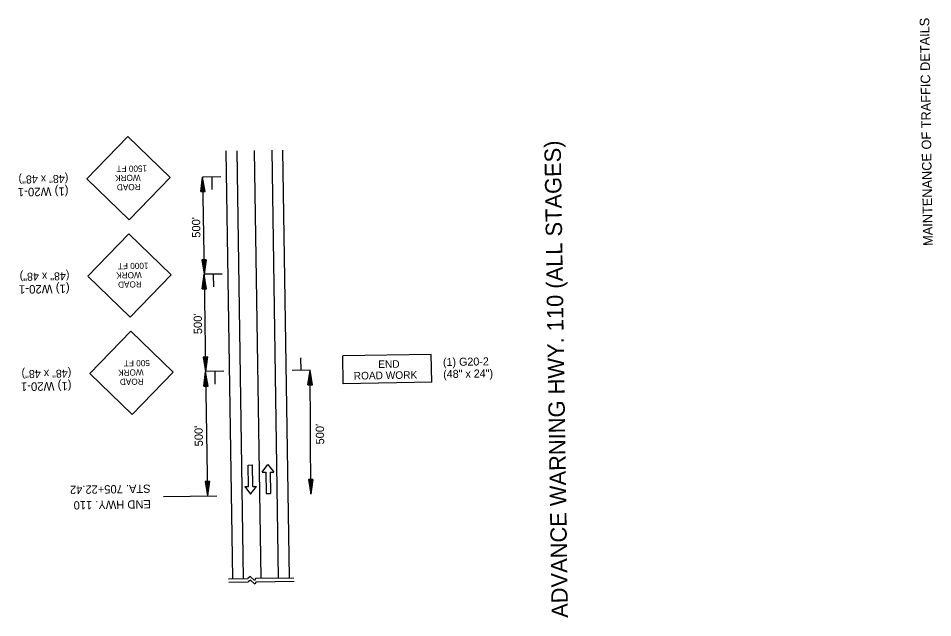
# Model space of a CAD drawing. Extents: x 1770018 to 1773492, y 718230 to 729141.
# Drawn here: x 1770380 to 1771052, y 721562 to 722002 of the extents above; entities that cross this region are included whole.
import ezdxf

# ---------------------------------------------------------------- set-up
doc = ezdxf.new("R2010")
doc.units = 0
for name, color, linetype in [('Default', 7, 'Continuous'), ('R_Border', 7, 'Continuous'), ('R_Dimension', 7, 'Continuous'), ('R_Draft', 7, 'Continuous'), ('R_MOT', 7, 'Continuous')]:
    doc.layers.add(name, color=color, linetype=linetype)

msp = doc.modelspace()

# ---------------------------------------------------------------- linework, layer by layer
at = {"layer": 'Default'}
for p, q in [((1770540.66, 721904.52), (1770545.5, 721590.55)), ((1770553.51, 721904.71), (1770558.35, 721590.75)), ((1770566.37, 721904.91), (1770571.21, 721590.95)), ((1770515.64, 721885.26), (1770516.74, 721813.84)), ((1770516.74, 721813.84), (1770517.84, 721742.42)), ((1770595.14, 721652.54), (1770594.52, 721743.41)), ((1770517.84, 721742.42), (1770519.25, 721651.18)), ((1770548.95, 721673.83), (1770552.16, 721673.88)), ((1770549.19, 721658.07), (1770548.95, 721673.83)), ((1770552.41, 721658.12), (1770552.16, 721673.88)), ((1770559.32, 721668.59), (1770563.52, 721674.22)), ((1770563.52, 721674.22), (1770567.89, 721668.72)), ((1770559.32, 721668.59), (1770562, 721668.63)), ((1770562, 721668.63), (1770562.24, 721652.87)), ((1770565.21, 721668.68), (1770567.89, 721668.72)), ((1770565.21, 721668.68), (1770565.46, 721652.92)), ((1770546.52, 721658.03), (1770549.19, 721658.07)), ((1770546.52, 721658.03), (1770550.89, 721652.54)), ((1770550.89, 721652.54), (1770555.09, 721658.16)), ((1770552.41, 721658.12), (1770555.09, 721658.16)), ((1770486.81, 721650.68), (1770526.09, 721651.28)), ((1770562.24, 721652.87), (1770565.46, 721652.92)), ((1770534.54, 721590.38), (1770548.75, 721590.6)), ((1770554.62, 721590.69), (1770582.69, 721591.13)), ((1770554.85, 721588.12), (1770582.73, 721588.55)), ((1770534.77, 721587.81), (1770548.97, 721588.03))]:
    msp.add_line(p, q, dxfattribs=at)
for points in [[(1770554.62, 721590.69), (1770553.66, 721589.03), (1770550.58, 721591.93), (1770548.75, 721590.6)], [(1770554.85, 721588.12), (1770553.89, 721586.45), (1770550.8, 721589.35), (1770548.97, 721588.03)]]:
    msp.add_lwpolyline(points, dxfattribs=at)
at = {"layer": 'R_Dimension'}
for p, q in [((1770532.66, 721904.39), (1770537.5, 721590.43)), ((1770574.37, 721905.04), (1770579.21, 721591.07))]:
    msp.add_line(p, q, dxfattribs=at)
at = {"layer": 'R_Draft'}
for p, q in [((1770514.2, 721874.53), (1770515.64, 721885.26)), ((1770517.41, 721874.58), (1770515.64, 721885.26)), ((1770514.47, 721874.53), (1770515.67, 721883.47)), ((1770514.74, 721874.53), (1770515.7, 721881.63)), ((1770515.01, 721874.54), (1770515.72, 721879.85)), ((1770515.29, 721874.54), (1770515.75, 721878.03)), ((1770517.15, 721874.57), (1770515.67, 721883.47)), ((1770516.87, 721874.57), (1770515.7, 721881.63)), ((1770516.6, 721874.56), (1770515.72, 721879.85)), ((1770516.33, 721874.56), (1770515.75, 721878.03)), ((1770514.2, 721874.53), (1770517.41, 721874.58)), ((1770515.55, 721874.55), (1770515.78, 721876.24)), ((1770516.06, 721874.55), (1770515.78, 721876.24)), ((1770518.18, 721824.58), (1770514.97, 721824.53)), ((1770514.97, 721824.53), (1770516.74, 721813.84)), ((1770515.24, 721824.54), (1770516.71, 721815.63)), ((1770515.51, 721824.54), (1770516.69, 721817.48)), ((1770515.78, 721824.54), (1770516.66, 721819.26)), ((1770516.05, 721824.55), (1770516.63, 721821.08)), ((1770516.32, 721824.55), (1770516.6, 721822.86)), ((1770516.83, 721824.56), (1770516.6, 721822.86)), ((1770517.1, 721824.56), (1770516.63, 721821.08)), ((1770517.37, 721824.57), (1770516.66, 721819.26)), ((1770517.64, 721824.57), (1770516.69, 721817.48)), ((1770517.92, 721824.58), (1770516.71, 721815.63)), ((1770518.18, 721824.58), (1770516.74, 721813.84)), ((1770515.3, 721803.11), (1770516.74, 721813.84)), ((1770515.57, 721803.11), (1770516.77, 721812.05)), ((1770515.84, 721803.11), (1770516.8, 721810.21)), ((1770518.51, 721803.16), (1770516.74, 721813.84)), ((1770518.25, 721803.15), (1770516.77, 721812.05)), ((1770517.97, 721803.15), (1770516.8, 721810.21)), ((1770516.11, 721803.12), (1770516.83, 721808.43)), ((1770516.39, 721803.12), (1770516.85, 721806.61)), ((1770516.65, 721803.13), (1770516.88, 721804.82)), ((1770517.7, 721803.14), (1770516.83, 721808.43)), ((1770517.43, 721803.14), (1770516.85, 721806.61)), ((1770517.16, 721803.13), (1770516.88, 721804.82)), ((1770515.3, 721803.11), (1770518.51, 721803.16)), ((1770519.28, 721753.16), (1770516.07, 721753.11)), ((1770516.07, 721753.11), (1770517.84, 721742.42)), ((1770516.34, 721753.12), (1770517.81, 721744.21)), ((1770516.61, 721753.12), (1770517.79, 721746.06)), ((1770516.88, 721753.12), (1770517.76, 721747.84)), ((1770517.15, 721753.13), (1770517.73, 721749.66)), ((1770517.43, 721753.13), (1770517.7, 721751.44)), ((1770517.93, 721753.14), (1770517.7, 721751.44)), ((1770518.2, 721753.14), (1770517.73, 721749.66)), ((1770518.48, 721753.15), (1770517.76, 721747.84)), ((1770518.74, 721753.15), (1770517.79, 721746.06)), ((1770519.02, 721753.16), (1770517.81, 721744.21)), ((1770519.28, 721753.16), (1770517.84, 721742.42)), ((1770592.98, 721732.69), (1770594.52, 721743.41)), ((1770596.2, 721732.71), (1770594.52, 721743.41)), ((1770516.4, 721731.69), (1770517.84, 721742.42)), ((1770516.67, 721731.69), (1770517.87, 721740.63)), ((1770516.94, 721731.69), (1770517.9, 721738.79)), ((1770517.21, 721731.7), (1770517.93, 721737.01)), ((1770519.61, 721731.74), (1770517.84, 721742.42)), ((1770519.35, 721731.73), (1770517.87, 721740.63)), ((1770519.07, 721731.73), (1770517.9, 721738.79)), ((1770518.81, 721731.72), (1770517.93, 721737.01)), ((1770593.25, 721732.69), (1770594.53, 721741.62)), ((1770593.53, 721732.69), (1770594.54, 721739.78)), ((1770593.79, 721732.69), (1770594.55, 721738)), ((1770594.07, 721732.69), (1770594.57, 721736.18)), ((1770595.93, 721732.71), (1770594.53, 721741.62)), ((1770595.66, 721732.71), (1770594.54, 721739.78)), ((1770595.39, 721732.7), (1770594.55, 721738)), ((1770595.12, 721732.7), (1770594.57, 721736.18)), ((1770516.4, 721731.69), (1770519.61, 721731.74)), ((1770517.49, 721731.7), (1770517.95, 721735.19)), ((1770517.76, 721731.71), (1770517.98, 721733.4)), ((1770518.53, 721731.72), (1770517.95, 721735.19)), ((1770518.26, 721731.71), (1770517.98, 721733.4)), ((1770592.98, 721732.69), (1770596.2, 721732.71)), ((1770594.34, 721732.7), (1770594.58, 721734.39)), ((1770594.84, 721732.7), (1770594.58, 721734.39)), ((1770596.59, 721663.28), (1770593.37, 721663.23)), ((1770593.37, 721663.23), (1770595.14, 721652.54)), ((1770593.64, 721663.24), (1770595.12, 721654.33)), ((1770593.91, 721663.24), (1770595.09, 721656.18)), ((1770594.18, 721663.24), (1770595.06, 721657.96)), ((1770594.45, 721663.25), (1770595.03, 721659.78)), ((1770594.73, 721663.25), (1770595.01, 721661.56)), ((1770595.23, 721663.26), (1770595.01, 721661.56)), ((1770595.5, 721663.26), (1770595.03, 721659.78)), ((1770595.78, 721663.27), (1770595.06, 721657.96)), ((1770596.05, 721663.27), (1770595.09, 721656.18)), ((1770596.32, 721663.28), (1770595.12, 721654.33)), ((1770596.59, 721663.28), (1770595.14, 721652.54)), ((1770520.69, 721661.92), (1770517.48, 721661.87)), ((1770517.48, 721661.87), (1770519.25, 721651.18)), ((1770517.74, 721661.87), (1770519.22, 721652.97)), ((1770518.02, 721661.87), (1770519.19, 721654.81)), ((1770518.28, 721661.88), (1770519.16, 721656.59)), ((1770518.56, 721661.88), (1770519.14, 721658.41)), ((1770518.83, 721661.89), (1770519.11, 721660.2)), ((1770519.33, 721661.9), (1770519.11, 721660.2)), ((1770519.6, 721661.9), (1770519.14, 721658.41)), ((1770519.88, 721661.9), (1770519.16, 721656.59)), ((1770520.15, 721661.91), (1770519.19, 721654.81)), ((1770520.42, 721661.91), (1770519.22, 721652.97)), ((1770520.69, 721661.92), (1770519.25, 721651.18))]:
    msp.add_line(p, q, dxfattribs=at)
at = {"layer": 'R_MOT'}
for p, q in [((1770430.49, 721883.95), (1770460.67, 721915.05)), ((1770460.67, 721915.05), (1770491.79, 721884.9)), ((1770430.49, 721883.95), (1770461.61, 721853.78)), ((1770461.61, 721853.78), (1770491.79, 721884.9)), ((1770528.88, 721885.47), (1770515.64, 721885.26)), ((1770522.3, 721885.17), (1770522.43, 721876.14)), ((1770431.33, 721812.53), (1770461.5, 721843.62)), ((1770461.5, 721843.62), (1770492.62, 721813.47)), ((1770431.33, 721812.53), (1770462.45, 721782.35)), ((1770462.45, 721782.35), (1770492.62, 721813.47)), ((1770529.98, 721814.05), (1770516.74, 721813.84)), ((1770523.4, 721813.75), (1770523.53, 721804.72)), ((1770432.7, 721741.11), (1770462.87, 721772.21)), ((1770462.87, 721772.21), (1770493.99, 721742.06)), ((1770587.93, 721743.5), (1770587.79, 721752.54)), ((1770683.57, 721755.01), (1770618.48, 721754.01)), ((1770618.79, 721733.56), (1770618.48, 721754.01)), ((1770683.88, 721734.56), (1770683.57, 721755.01)), ((1770594.52, 721743.41), (1770581.28, 721743.21)), ((1770432.7, 721741.11), (1770463.81, 721710.94)), ((1770463.81, 721710.94), (1770493.99, 721742.06)), ((1770531.08, 721742.63), (1770517.84, 721742.42)), ((1770524.5, 721742.33), (1770524.63, 721733.3)), ((1770683.88, 721734.56), (1770618.79, 721733.56))]:
    msp.add_line(p, q, dxfattribs=at)

# ---------------------------------------------------------------- texts
at = {"layer": 'Default'}
for s, rotation, p in [("500'", 90.88269, (1770514.02, 721840.72)), ("500'", 90.88269, (1770515.27, 721769.94)), ("500'", 90.88269, (1770604.94, 721688.96)), ("500'", 90.88269, (1770515.89, 721687.59)), ('STA. 705+22.42', 180.88269, (1770477.34, 721659.53)), ('END HWY. 110', 180.88269, (1770477.51, 721648.14))]:
    msp.add_text(s, height=6.1, rotation=rotation, dxfattribs=at).set_placement(p)
at = {"layer": 'R_Border'}
msp.add_text('MAINTENANCE OF TRAFFIC DETAILS', height=7, rotation=90.88269, dxfattribs=at).set_placement((1771051.86, 721834.77))
at = {"layer": 'R_Draft'}
msp.add_text('ADVANCE WARNING HWY. 110 (ALL STAGES)', height=12, rotation=90.88269, dxfattribs=at).set_placement((1770783.98, 721561.74))
at = {"layer": 'R_MOT'}
for s, height, rotation, p in [('1500 FT', 4.516, 180.88326, (1770474.81, 721893.82)), ('(48" x 48")', 5.88, 180.88269, (1770416.96, 721886.84)), ('WORK', 4.515, 180.88272, (1770470.05, 721886.97)), ('(1) W20-1', 6.273, 180.88269, (1770417.1, 721877.81)), ('ROAD', 4.516, 180.88314, (1770470.06, 721880.2)), ('(48" x 48")', 5.88, 180.88269, (1770417.8, 721815.42)), ('1000 FT', 4.516, 180.88326, (1770475.83, 721822.4)), ('WORK', 4.515, 180.88272, (1770470.88, 721815.54)), ('(1) W20-1', 6.273, 180.88269, (1770417.94, 721806.39)), ('ROAD', 4.516, 180.88314, (1770470.9, 721808.77)), (' 500 FT', 4.516, 180.88326, (1770478.52, 721751)), ('END', 5.557, 0.88269, (1770644.64, 721745.05)), ('(1) G20-2', 5.881, 0.88269, (1770692.2, 721746.5)), ('(48" x 48")', 5.88, 180.88269, (1770419.16, 721744)), ('WORK', 4.515, 180.88272, (1770472.25, 721744.13)), ('ROAD WORK', 5.557, 0.88269, (1770626.63, 721736.56)), ('(48" x 24")', 5.88, 0.88269, (1770692.34, 721737.69)), ('(1) W20-1', 6.273, 180.88269, (1770419.3, 721734.97)), ('ROAD', 4.516, 180.88314, (1770472.26, 721737.35))]:
    msp.add_text(s, height=height, rotation=rotation, dxfattribs=at).set_placement(p)

doc.saveas('drawing.dxf')
